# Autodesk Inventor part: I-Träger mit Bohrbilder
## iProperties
Shininess: 64.0
Length Units: 11269
Angle Units: 11279
Time Units: 11290
Mass Units: 11283
Length Display Precision: 3
Angle Display Precision: 2
Compacted: True
Part Number: I-Träger mit Bohrbilder
Document SubType Name: Modeling
Created: 2003-11
Material: Standard
Designer: Sauer
Manufacturer: Standard
Standards Organization: Custom
Density: 0.0
Volumn: 0.0
Area: 0.0
PropertySet Name: Model Information
Control State: 0
Master: False
Checked Out: False
Author: Sauer
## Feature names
1. Extrusion1
2. LB1 [Extrusion]
3. SLB1 [Mirror]
4. LB2 [Extrusion]
5. SLB2 [Mirror]
